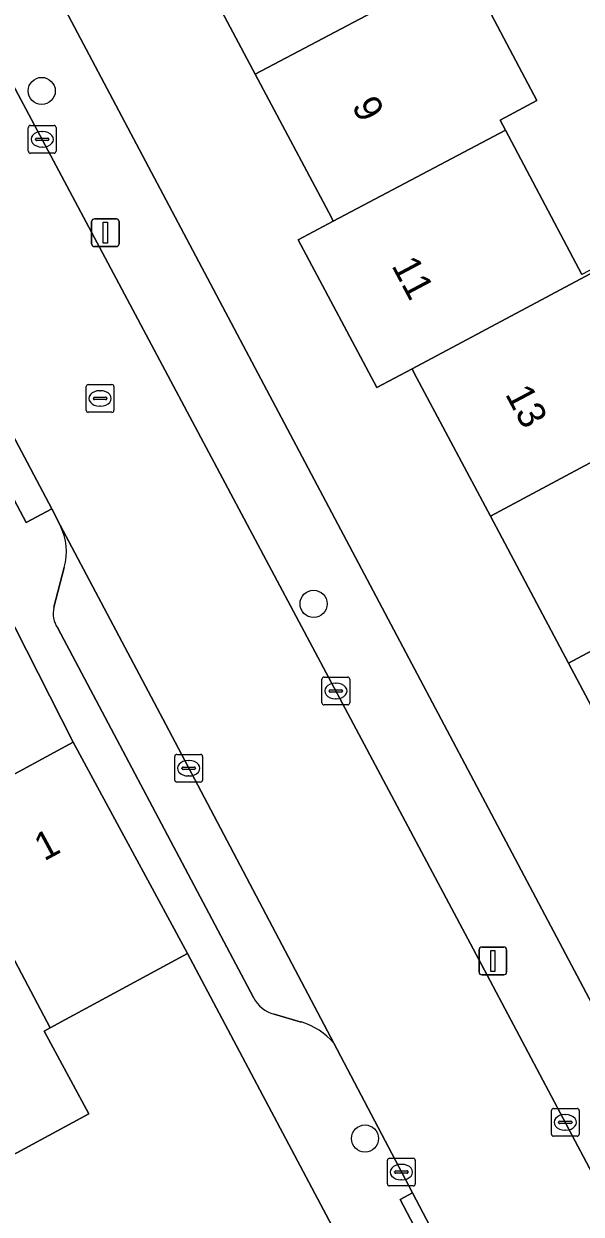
# Model space of a CAD drawing. Extents: x 157320 to 158835, y 386650 to 388491.
# Drawn here: x 157713.52 to 157733.59, y 387593.4 to 387636.29 of the extents above; entities that cross this region are included whole.
import ezdxf

# ---------------------------------------------------------------- set-up
doc = ezdxf.new("R2010")
doc.units = 0
for name, color, linetype in [('IMGEO_Boom', 7, 'Continuous'), ('IMGEO_Erf', 7, 'Continuous'), ('IMGEO_Kolk', 7, 'Continuous'), ('IMGEO_Lichtmast', 7, 'Continuous'), ('IMGEO_Pand', 7, 'Continuous'), ('IMGEO_Pand_nummerreeks', 7, 'Continuous'), ('IMGEO_Parkeervlak_open', 7, 'Continuous'), ('IMGEO_Rijbaan_lokaal_open', 7, 'Continuous'), ('IMGEO_Rioolput', 7, 'Continuous'), ('IMGEO_Voetpad_open', 7, 'Continuous')]:
    doc.layers.add(name, color=color, linetype=linetype)

msp = doc.modelspace()

# ---------------------------------------------------------------- linework, layer by layer
at = {"layer": 'IMGEO_Boom'}
for centre in [(157714.164, 387633.872), (157723.954, 387615.389), (157725.805, 387596.124)]:
    msp.add_circle(centre, 0.489, dxfattribs=at)
at = {"layer": 'IMGEO_Erf'}
for points in [[(157705.212, 387655.297), (157737.182, 387594.934), (157737.199, 387594.901), (157741.611, 387597.243), (157738.8, 387602.537), (157738.734, 387602.661), (157737.424, 387601.963), (157734.629, 387607.226), (157735.954, 387607.939), (157735.893, 387608.055), (157733.136, 387613.247), (157730.322, 387618.545), (157727.568, 387623.732), (157727.501, 387623.859), (157726.228, 387623.18), (157723.396, 387628.511), (157724.662, 387629.181), (157724.595, 387629.308), (157721.853, 387634.472), (157719.051, 387639.747)], [(157729.385, 387638.462), (157731.995, 387633.523), (157730.669, 387632.823), (157730.86, 387632.461), (157733.613, 387627.253)], [(157683.592, 387573.291), (157686.623, 387577.758), (157689.656, 387582.226), (157692.687, 387586.693), (157695.719, 387591.162), (157698.751, 387595.629), (157701.836, 387600.175), (157703.199, 387599.386), (157704.915, 387601.899), (157706.636, 387602.828), (157705.427, 387605.064), (157710.429, 387607.767), (157715.302, 387610.401), (157712.78, 387615.384), (157707.158, 387612.356), (157706.257, 387611.54), (157692.204, 387591.043), (157667.746, 387555.368)], [(157727.739, 387587.082), (157719.417, 387602.787), (157715.019, 387600.41), (157714.466, 387600.111), (157714.252, 387599.996), (157715.862, 387597.016), (157711.531, 387594.676), (157709.921, 387597.655), (157709.609, 387597.486), (157710.084, 387596.608), (157709.21, 387595.329), (157709.14, 387595.226), (157710.829, 387594.072), (157713.365, 387592.357)]]:
    msp.add_lwpolyline(points, dxfattribs=at)
at = {"layer": 'IMGEO_Kolk'}
for p, q in [((157713.757, 387632.629), (157714.609, 387632.629)), ((157713.682, 387631.703), (157713.682, 387632.555)), ((157713.984, 387632.172), (157714.382, 387632.172)), ((157714.17, 387632.409), (157714.195, 387632.409)), ((157714.683, 387632.555), (157714.683, 387631.703)), ((157713.941, 387632.123), (157713.941, 387632.135)), ((157714.379, 387632.086), (157713.981, 387632.086)), ((157714.193, 387631.849), (157714.168, 387631.849)), ((157714.425, 387632.135), (157714.425, 387632.123)), ((157714.609, 387631.629), (157713.757, 387631.629)), ((157724.256, 387611.823), (157724.256, 387612.675)), ((157724.331, 387612.749), (157725.183, 387612.749)), ((157724.744, 387612.529), (157724.769, 387612.529)), ((157725.257, 387612.675), (157725.257, 387611.823)), ((157724.515, 387612.243), (157724.515, 387612.255)), ((157724.953, 387612.206), (157724.555, 387612.206)), ((157724.558, 387612.292), (157724.956, 387612.292)), ((157724.999, 387612.255), (157724.999, 387612.243)), ((157725.183, 387611.749), (157724.331, 387611.749)), ((157724.767, 387611.969), (157724.742, 387611.969)), ((157718.956, 387609.041), (157718.956, 387609.893)), ((157719.031, 387609.967), (157719.883, 387609.967)), ((157719.957, 387609.893), (157719.957, 387609.041)), ((157719.215, 387609.461), (157719.215, 387609.473)), ((157719.258, 387609.51), (157719.656, 387609.51)), ((157719.444, 387609.747), (157719.469, 387609.747)), ((157719.699, 387609.473), (157719.699, 387609.461)), ((157719.653, 387609.424), (157719.255, 387609.424)), ((157719.467, 387609.187), (157719.442, 387609.187)), ((157719.883, 387608.967), (157719.031, 387608.967)), ((157732.517, 387596.28), (157732.517, 387597.132)), ((157732.592, 387597.206), (157733.444, 387597.206)), ((157733.518, 387597.132), (157733.518, 387596.28)), ((157732.776, 387596.7), (157732.776, 387596.712)), ((157733.214, 387596.663), (157732.816, 387596.663)), ((157732.819, 387596.749), (157733.217, 387596.749)), ((157733.005, 387596.986), (157733.03, 387596.986)), ((157733.26, 387596.712), (157733.26, 387596.7)), ((157733.444, 387596.206), (157732.592, 387596.206)), ((157733.028, 387596.426), (157733.003, 387596.426)), ((157726.614, 387594.488), (157726.614, 387595.34)), ((157726.689, 387595.414), (157727.541, 387595.414)), ((157727.615, 387595.34), (157727.615, 387594.488)), ((157726.873, 387594.908), (157726.873, 387594.92)), ((157727.311, 387594.871), (157726.913, 387594.871)), ((157726.916, 387594.957), (157727.314, 387594.957)), ((157727.102, 387595.194), (157727.127, 387595.194)), ((157727.357, 387594.92), (157727.357, 387594.908)), ((157727.125, 387594.634), (157727.1, 387594.634)), ((157727.541, 387594.414), (157726.689, 387594.414))]:
    msp.add_line(p, q, dxfattribs=at)
for points in [[(157713.757, 387632.629), (157714.609, 387632.629)], [(157713.682, 387631.703), (157713.682, 387632.555)], [(157714.683, 387632.555), (157714.683, 387631.703)], [(157714.609, 387631.629), (157713.757, 387631.629)], [(157724.256, 387611.823), (157724.256, 387612.675)], [(157724.331, 387612.749), (157725.183, 387612.749)], [(157725.257, 387612.675), (157725.257, 387611.823)], [(157725.183, 387611.749), (157724.331, 387611.749)], [(157718.956, 387609.041), (157718.956, 387609.893)], [(157719.031, 387609.967), (157719.883, 387609.967)], [(157719.957, 387609.893), (157719.957, 387609.041)], [(157719.883, 387608.967), (157719.031, 387608.967)], [(157732.517, 387596.28), (157732.517, 387597.132)], [(157732.592, 387597.206), (157733.444, 387597.206)], [(157733.518, 387597.132), (157733.518, 387596.28)], [(157733.444, 387596.206), (157732.592, 387596.206)], [(157726.614, 387594.488), (157726.614, 387595.34)], [(157726.689, 387595.414), (157727.541, 387595.414)], [(157727.615, 387595.34), (157727.615, 387594.488)], [(157727.541, 387594.414), (157726.689, 387594.414)]]:
    msp.add_lwpolyline(points, dxfattribs=at)
for centre, radius, start, end in [((157713.759, 387632.553), 0.0765, 91.552, 178.448), ((157713.759, 387632.553), 0.0765, 91.552, 178.448), ((157714.607, 387632.553), 0.0765, 1.552, 88.448), ((157714.607, 387632.553), 0.0765, 1.552, 88.448), ((157713.981, 387632.132), 0.0403, 85.8775, 175.7526), ((157714.386, 387632.134), 0.0386, 1.7309, 96.639), ((157713.978, 387632.122), 0.0366, 178.938, 274.7102), ((157714.382, 387632.129), 0.043, 264.8664, 352.4533), ((157713.759, 387631.705), 0.0765, 181.552, 268.448), ((157713.759, 387631.705), 0.0765, 181.552, 268.448), ((157714.607, 387631.705), 0.0765, 271.552, 358.448), ((157714.607, 387631.705), 0.0765, 271.552, 358.448), ((157724.333, 387612.673), 0.0765, 91.552, 178.448), ((157724.333, 387612.673), 0.0765, 91.552, 178.448), ((157725.181, 387612.673), 0.0765, 1.552, 88.448), ((157725.181, 387612.673), 0.0765, 1.552, 88.448), ((157724.555, 387612.252), 0.0403, 85.8775, 175.7526), ((157724.552, 387612.242), 0.0366, 178.938, 274.7102), ((157724.956, 387612.249), 0.043, 264.8664, 352.4533), ((157724.96, 387612.254), 0.0386, 1.7309, 96.639), ((157724.333, 387611.825), 0.0765, 181.552, 268.448), ((157724.333, 387611.825), 0.0765, 181.552, 268.448), ((157725.181, 387611.825), 0.0765, 271.552, 358.448), ((157725.181, 387611.825), 0.0765, 271.552, 358.448), ((157719.033, 387609.891), 0.0765, 91.552, 178.448), ((157719.033, 387609.891), 0.0765, 91.552, 178.448), ((157719.881, 387609.891), 0.0765, 1.552, 88.448), ((157719.881, 387609.891), 0.0765, 1.552, 88.448), ((157719.255, 387609.47), 0.0403, 85.8775, 175.7526), ((157719.252, 387609.46), 0.0366, 178.938, 274.7102), ((157719.656, 387609.467), 0.043, 264.8664, 352.4533), ((157719.66, 387609.472), 0.0386, 1.7309, 96.639), ((157719.033, 387609.043), 0.0765, 181.552, 268.448), ((157719.033, 387609.043), 0.0765, 181.552, 268.448), ((157719.881, 387609.043), 0.0765, 271.552, 358.448), ((157719.881, 387609.043), 0.0765, 271.552, 358.448), ((157732.594, 387597.13), 0.0765, 91.552, 178.448), ((157732.594, 387597.13), 0.0765, 91.552, 178.448), ((157733.442, 387597.13), 0.0765, 1.552, 88.448), ((157733.442, 387597.13), 0.0765, 1.552, 88.448), ((157732.816, 387596.709), 0.0403, 85.8775, 175.7526), ((157732.813, 387596.699), 0.0366, 178.938, 274.7102), ((157733.217, 387596.706), 0.043, 264.8664, 352.4533), ((157733.221, 387596.711), 0.0386, 1.7309, 96.639), ((157732.594, 387596.282), 0.0765, 181.552, 268.448), ((157732.594, 387596.282), 0.0765, 181.552, 268.448), ((157733.442, 387596.282), 0.0765, 271.552, 358.448), ((157733.442, 387596.282), 0.0765, 271.552, 358.448), ((157726.691, 387595.338), 0.0765, 91.552, 178.448), ((157726.691, 387595.338), 0.0765, 91.552, 178.448), ((157727.539, 387595.338), 0.0765, 1.552, 88.448), ((157727.539, 387595.338), 0.0765, 1.552, 88.448), ((157726.913, 387594.917), 0.0403, 85.8775, 175.7526), ((157726.91, 387594.907), 0.0366, 178.938, 274.7102), ((157727.314, 387594.914), 0.043, 264.8664, 352.4533), ((157727.318, 387594.919), 0.0386, 1.7309, 96.639), ((157726.691, 387594.49), 0.0765, 181.552, 268.448), ((157726.691, 387594.49), 0.0765, 181.552, 268.448), ((157727.539, 387594.49), 0.0765, 271.552, 358.448), ((157727.539, 387594.49), 0.0765, 271.552, 358.448)]:
    msp.add_arc(centre, radius, start, end, dxfattribs=at)
for centre, major_axis, ratio, start_param, end_param in [((157714.169, 387632.129), (-0.387, 0.002), 0.722429, 4.712389, 7.853982), ((157714.194, 387632.129), (-0.39, 0.002), 0.717154, 1.570796, 4.712389), ((157724.743, 387612.249), (-0.387, 0.002), 0.722429, 4.712389, 7.853982), ((157724.768, 387612.249), (-0.39, 0.002), 0.717154, 1.570796, 4.712389), ((157719.443, 387609.467), (-0.387, 0.002), 0.722429, 4.712389, 7.853982), ((157719.468, 387609.467), (-0.39, 0.002), 0.717154, 1.570796, 4.712389), ((157733.004, 387596.706), (-0.387, 0.002), 0.722429, 4.712389, 7.853982), ((157733.029, 387596.706), (-0.39, 0.002), 0.717154, 1.570796, 4.712389), ((157727.101, 387594.914), (-0.387, 0.002), 0.722429, 4.712389, 7.853982), ((157727.126, 387594.914), (-0.39, 0.002), 0.717154, 1.570796, 4.712389)]:
    msp.add_ellipse(centre, major_axis=major_axis, ratio=ratio, start_param=start_param, end_param=end_param, dxfattribs=at)
at = {"layer": 'IMGEO_Lichtmast'}
for p, q in [((157716.062, 387629.263), (157716.852, 387629.263)), ((157716.852, 387629.263), (157716.062, 387629.263)), ((157715.962, 387628.363), (157715.962, 387629.163)), ((157715.962, 387629.163), (157715.962, 387628.363)), ((157716.952, 387629.163), (157716.952, 387628.363)), ((157716.952, 387628.363), (157716.952, 387629.163)), ((157716.852, 387628.263), (157716.062, 387628.263)), ((157716.062, 387628.263), (157716.852, 387628.263)), ((157730.012, 387603.021), (157730.802, 387603.021)), ((157730.802, 387603.021), (157730.012, 387603.021)), ((157729.912, 387602.121), (157729.912, 387602.921)), ((157729.912, 387602.921), (157729.912, 387602.121)), ((157730.902, 387602.921), (157730.902, 387602.121)), ((157730.902, 387602.121), (157730.902, 387602.921)), ((157730.802, 387602.021), (157730.012, 387602.021)), ((157730.012, 387602.021), (157730.802, 387602.021))]:
    msp.add_line(p, q, dxfattribs=at)
for points in [[(157716.382, 387629.138), (157716.532, 387629.138), (157716.532, 387628.388), (157716.382, 387628.388), (157716.382, 387629.138)], [(157730.332, 387602.896), (157730.482, 387602.896), (157730.482, 387602.146), (157730.332, 387602.146), (157730.332, 387602.896)]]:
    msp.add_lwpolyline(points, dxfattribs=at)
for centre, start, end in [((157716.062, 387629.163), 90, 180), ((157716.062, 387629.163), 90, 180), ((157716.852, 387629.163), 0, 90), ((157716.852, 387629.163), 360, 90), ((157716.062, 387628.363), 180, 270), ((157716.062, 387628.363), 180, 270), ((157716.852, 387628.363), 270, 0), ((157716.852, 387628.363), 270, 0), ((157730.012, 387602.921), 90, 180), ((157730.012, 387602.921), 90, 180), ((157730.802, 387602.921), 0, 90), ((157730.802, 387602.921), 360, 90), ((157730.012, 387602.121), 180, 270), ((157730.012, 387602.121), 180, 270), ((157730.802, 387602.121), 270, 0), ((157730.802, 387602.121), 270, 0)]:
    msp.add_arc(centre, 0.1, start, end, dxfattribs=at)
at = {"layer": 'IMGEO_Pand'}
for points in [[(157721.853, 387634.472), (157729.385, 387638.462), (157726.585, 387643.761), (157719.051, 387639.747)], [(157730.86, 387632.461), (157730.669, 387632.823), (157731.995, 387633.523), (157729.385, 387638.462), (157721.853, 387634.472), (157724.595, 387629.308), (157724.662, 387629.181)], [(157734.991, 387627.855), (157734.939, 387627.953), (157733.613, 387627.253), (157730.86, 387632.461), (157724.662, 387629.181), (157723.396, 387628.511), (157726.228, 387623.18), (157727.501, 387623.859)], [(157734.991, 387627.855), (157727.501, 387623.859), (157727.568, 387623.732), (157730.322, 387618.545), (157737.792, 387622.555)], [(157737.792, 387622.555), (157730.322, 387618.545), (157733.136, 387613.247), (157740.593, 387617.255)], [(157742.078, 387611.236), (157742.006, 387611.373), (157743.332, 387612.073), (157740.593, 387617.255), (157733.136, 387613.247), (157735.893, 387608.055), (157735.954, 387607.939)], [(157710.429, 387607.767), (157714.466, 387600.111), (157715.019, 387600.41), (157719.417, 387602.787), (157715.302, 387610.401)], [(157710.429, 387607.767), (157705.427, 387605.064), (157706.636, 387602.828), (157704.915, 387601.899), (157703.199, 387599.386), (157709.21, 387595.329), (157710.084, 387596.608), (157709.609, 387597.486), (157709.921, 387597.655), (157711.531, 387594.676), (157715.862, 387597.016), (157714.252, 387599.996), (157714.466, 387600.111)]]:
    msp.add_lwpolyline(points, close=True, dxfattribs=at)
at = {"layer": 'IMGEO_Parkeervlak_open'}
for points in [[(157724.678, 387599.557), (157718.741, 387610.836), (157714.825, 387618.222)], [(157714.974, 387616.695), (157714.598, 387615.265)], [(157714.739, 387614.519), (157717.196, 387609.885), (157721.787, 387601.203)], [(157722.535, 387600.604), (157723.512, 387600.322)]]:
    msp.add_lwpolyline(points, dxfattribs=at)
for centre, radius, start, end in [((157712.941, 387617.267), 2.112, 344.277, 26.8692), ((157715.565, 387615.061), 0.988, 168.1172, 213.2891), ((157722.827, 387601.735), 1.168, 207.0844, 255.5399), ((157722.818, 387597.994), 2.43, 40.0535, 73.4096)]:
    msp.add_arc(centre, radius, start, end, dxfattribs=at)
at = {"layer": 'IMGEO_Rijbaan_lokaal_open'}
for points in [[(157739.744, 387584.027), (157735.466, 387592.089), (157729.998, 387602.392), (157713.019, 387634.314), (157706.841, 387645.947)], [(157704.707, 387637.298), (157708.819, 387629.59), (157711.79, 387623.962), (157714.525, 387618.81), (157714.825, 387618.222), (157718.741, 387610.836), (157724.678, 387599.557), (157727.511, 387594.161), (157732.446, 387584.764), (157733.945, 387581.909), (157734.292, 387581.255)]]:
    msp.add_lwpolyline(points, dxfattribs=at)
at = {"layer": 'IMGEO_Rioolput'}
for p, q in [((157715.765, 387622.365), (157715.765, 387623.217)), ((157715.84, 387623.291), (157716.692, 387623.291)), ((157716.766, 387623.217), (157716.766, 387622.365)), ((157716.024, 387622.785), (157716.024, 387622.797)), ((157716.462, 387622.748), (157716.064, 387622.748)), ((157716.067, 387622.834), (157716.465, 387622.834)), ((157716.253, 387623.071), (157716.278, 387623.071)), ((157716.508, 387622.797), (157716.508, 387622.785)), ((157716.276, 387622.511), (157716.251, 387622.511)), ((157716.692, 387622.291), (157715.84, 387622.291))]:
    msp.add_line(p, q, dxfattribs=at)
for points in [[(157715.765, 387622.365), (157715.765, 387623.217)], [(157715.84, 387623.291), (157716.692, 387623.291)], [(157716.766, 387623.217), (157716.766, 387622.365)], [(157716.692, 387622.291), (157715.84, 387622.291)]]:
    msp.add_lwpolyline(points, dxfattribs=at)
for centre, radius, start, end in [((157715.842, 387623.215), 0.0765, 91.552, 178.448), ((157715.842, 387623.215), 0.0765, 91.552, 178.448), ((157716.69, 387623.215), 0.0765, 1.552, 88.448), ((157716.69, 387623.215), 0.0765, 1.552, 88.448), ((157716.064, 387622.794), 0.0403, 85.8775, 175.7526), ((157716.061, 387622.784), 0.0366, 178.938, 274.7102), ((157716.465, 387622.791), 0.043, 264.8664, 352.4533), ((157716.469, 387622.796), 0.0386, 1.7309, 96.639), ((157715.842, 387622.367), 0.0765, 181.552, 268.448), ((157715.842, 387622.367), 0.0765, 181.552, 268.448), ((157716.69, 387622.367), 0.0765, 271.552, 358.448), ((157716.69, 387622.367), 0.0765, 271.552, 358.448)]:
    msp.add_arc(centre, radius, start, end, dxfattribs=at)
for centre, major_axis, ratio, start_param, end_param in [((157716.252, 387622.791), (-0.387, 0.002), 0.722429, 4.712389, 7.853982), ((157716.277, 387622.791), (-0.39, 0.002), 0.717154, 1.570796, 4.712389)]:
    msp.add_ellipse(centre, major_axis=major_axis, ratio=ratio, start_param=start_param, end_param=end_param, dxfattribs=at)
at = {"layer": 'IMGEO_Voetpad_open'}
for points in [[(157686.238, 387685.019), (157687.095, 387683.297), (157688.746, 387680.168), (157699.49, 387659.747), (157700.408, 387660.236), (157704.096, 387653.313), (157703.178, 387652.824), (157706.841, 387645.947), (157713.019, 387634.314), (157729.998, 387602.392), (157735.466, 387592.089), (157735.907, 387592.323), (157740.185, 387584.261), (157739.744, 387584.027), (157740.957, 387581.742)], [(157753.882, 387564.534), (157757.353, 387567.196), (157749.094, 387577.728), (157740.98, 387588.074), (157739.961, 387589.687), (157737.93, 387593.521), (157737.92, 387593.54), (157737.199, 387594.901), (157737.182, 387594.934), (157705.212, 387655.297)], [(157714.825, 387618.222), (157714.525, 387618.81), (157713.606, 387618.322), (157711.124, 387622.997), (157710.561, 387622.698), (157710.003, 387622.401), (157712.088, 387618.361), (157711.546, 387618.057), (157712.78, 387615.384), (157715.302, 387610.401), (157719.417, 387602.787), (157727.739, 387587.082), (157728.437, 387585.765), (157731.431, 387580.114), (157730.809, 387577.363), (157746.726, 387556.998), (157749.611, 387553.306), (157750.654, 387551.925), (157752.186, 387553.14), (157752.394, 387553.414), (157752.798, 387553.945)], [(157714.598, 387615.265), (157714.974, 387616.695)], [(157721.787, 387601.203), (157717.196, 387609.885), (157714.739, 387614.519)], [(157723.512, 387600.322), (157722.535, 387600.604)], [(157727.069, 387593.929), (157727.511, 387594.161), (157724.678, 387599.557)], [(157734.292, 387581.255), (157733.945, 387581.909), (157732.446, 387584.764), (157732.004, 387584.532), (157727.069, 387593.929)]]:
    msp.add_lwpolyline(points, dxfattribs=at)
for points in [[(157711.79, 387623.962), (157710.871, 387623.474), (157711.124, 387622.997), (157713.606, 387618.322), (157714.525, 387618.81)], [(157732.446, 387584.764), (157727.511, 387594.161), (157727.069, 387593.929), (157732.004, 387584.532)]]:
    msp.add_lwpolyline(points, close=True, dxfattribs=at)
for centre, radius, start, end in [((157712.941, 387617.267), 2.112, 344.277, 26.8692), ((157715.565, 387615.061), 0.988, 168.1172, 213.2891), ((157722.827, 387601.735), 1.168, 207.0844, 255.5399), ((157722.818, 387597.994), 2.43, 40.0535, 73.4096)]:
    msp.add_arc(centre, radius, start, end, dxfattribs=at)

# ---------------------------------------------------------------- texts
at = {"layer": 'IMGEO_Pand_nummerreeks'}
for s, rotation, p in [('9', 297.9716, (157725.31, 387633.334)), ('11', 297.9773, (157726.746, 387627.576)), ('13', 297.9716, (157730.837, 387622.95)), ('1', 28.3893, (157714.251, 387606.105))]:
    msp.add_text(s, height=1, rotation=rotation, dxfattribs=at).set_placement(p)

doc.saveas('drawing.dxf')
